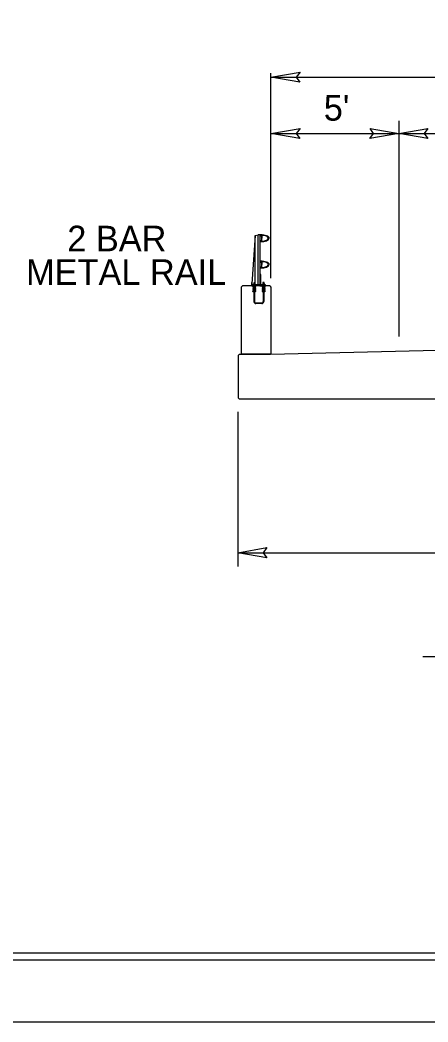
# Model space of a CAD drawing. Extents: x 1734085 to 1734267, y 541107 to 541226.
# Drawn here: x 1734191.61 to 1734207.51, y 541107.08 to 541146.16 of the extents above; entities that cross this region are included whole.
import ezdxf

# ---------------------------------------------------------------- set-up
doc = ezdxf.new("R2010")
doc.units = 0
for name, color, linetype in [('Default', 7, 'Continuous'), ('Prop Dimension', 7, 'Continuous'), ('Prop Terminator CELL', 7, 'Continuous'), ('Sheet Cutting Line CELL', 7, 'Continuous'), ('Sheet Plot Border Inside CELL', 7, 'Continuous'), ('Sheet Plot Border Outside CELL', 7, 'Continuous'), ('Sheet Typical CELL', 7, 'Continuous'), ('Typical Bridge Rail Two Bar CELL', 7, 'Continuous'), ('Typical Slope Point Local CELL', 7, 'Continuous'), ('Typical Text Label CELL', 7, 'Continuous')]:
    doc.layers.add(name, color=color, linetype=linetype)

msp = doc.modelspace()

# ---------------------------------------------------------------- linework, layer by layer
at = {"layer": 'Default'}
for p, q in [((1734200.102, 541130.874), (1734200.102, 541124.844)), ((1734200.102, 541125.381), (1734236.662, 541125.381))]:
    msp.add_line(p, q, dxfattribs=at)
at = {"layer": 'Prop Dimension'}
for p, q in [((1734201.393, 541136.094), (1734201.393, 541144.088)), ((1734201.393, 541143.929), (1734235.365, 541143.929)), ((1734206.379, 541142.237), (1734206.379, 541133.819)), ((1734201.393, 541141.737), (1734206.379, 541141.737)), ((1734206.379, 541141.737), (1734218.381, 541141.737))]:
    msp.add_line(p, q, dxfattribs=at)
at = {"layer": 'Prop Terminator CELL'}
for points in [[(1734202.518, 541143.735), (1734201.393, 541143.929), (1734202.524, 541144.129), (1734202.38, 541143.929)], [(1734202.518, 541141.543), (1734201.393, 541141.737), (1734202.524, 541141.937), (1734202.38, 541141.737)], [(1734205.254, 541141.931), (1734206.379, 541141.737), (1734205.247, 541141.537), (1734205.391, 541141.737)], [(1734207.504, 541141.543), (1734206.379, 541141.737), (1734207.51, 541141.937), (1734207.366, 541141.737)], [(1734201.227, 541125.188), (1734200.102, 541125.381), (1734201.233, 541125.581), (1734201.089, 541125.381)]]:
    msp.add_lwpolyline(points, close=True, dxfattribs=at)
at = {"layer": 'Sheet Cutting Line CELL'}
msp.add_line((1734084.641, 541107.075), (1734266.513, 541107.075), dxfattribs=at)
at = {"layer": 'Sheet Plot Border Inside CELL'}
msp.add_lwpolyline([(1734266.027, 541223.451), (1734086.045, 541223.451), (1734086.045, 541109.5), (1734266.027, 541109.5)], close=True, dxfattribs=at)
at = {"layer": 'Sheet Plot Border Outside CELL'}
msp.add_lwpolyline([(1734266.513, 541225.875), (1734084.641, 541225.875), (1734084.641, 541107.075), (1734266.513, 541107.075)], close=True, dxfattribs=at)
at = {"layer": 'Sheet Typical CELL'}
msp.add_lwpolyline([(1734264.677, 541223.175), (1734102.677, 541223.175), (1734102.677, 541109.775), (1734264.677, 541109.775)], close=True, dxfattribs=at)
at = {"layer": 'Typical Bridge Rail Two Bar CELL'}
for p, q in [((1734200.778, 541137.751), (1734200.641, 541135.868)), ((1734200.778, 541137.751), (1734200.897, 541137.789)), ((1734200.778, 541135.829), (1734200.778, 541137.751)), ((1734200.975, 541137.789), (1734200.897, 541137.789)), ((1734200.897, 541135.829), (1734200.897, 541137.789)), ((1734200.975, 541135.829), (1734200.975, 541137.789)), ((1734201.041, 541137.757), (1734201.041, 541137.65)), ((1734201.041, 541137.544), (1734201.041, 541137.65)), ((1734200.778, 541136.851), (1734200.774, 541136.851)), ((1734201.041, 541136.729), (1734201.041, 541136.623)), ((1734201.041, 541136.516), (1734201.041, 541136.623)), ((1734200.226, 541135.739), (1734200.277, 541135.789)), ((1734201.342, 541135.789), (1734200.277, 541135.789)), ((1734200.641, 541135.829), (1734200.641, 541135.868)), ((1734200.645, 541135.89), (1734200.645, 541135.924)), ((1734200.717, 541135.742), (1734200.717, 541135.829)), ((1734200.762, 541135.908), (1734200.718, 541135.908)), ((1734200.718, 541135.908), (1734200.718, 541135.871)), ((1734200.762, 541135.871), (1734200.762, 541135.908)), ((1734200.762, 541135.742), (1734200.762, 541135.829)), ((1734201.078, 541135.752), (1734201.078, 541135.839)), ((1734201.126, 541135.918), (1734201.081, 541135.918)), ((1734201.081, 541135.918), (1734201.081, 541135.881)), ((1734201.126, 541135.881), (1734201.126, 541135.918)), ((1734201.128, 541135.752), (1734201.128, 541135.839)), ((1734201.342, 541135.789), (1734201.393, 541135.739)), ((1734200.226, 541135.739), (1734200.226, 541133.123)), ((1734200.791, 541135.752), (1734200.687, 541135.752)), ((1734200.791, 541135.74), (1734200.687, 541135.74)), ((1734200.73, 541135.706), (1734200.687, 541135.706)), ((1734200.73, 541135.694), (1734200.687, 541135.694)), ((1734200.73, 541135.659), (1734200.687, 541135.659)), ((1734200.73, 541135.647), (1734200.687, 541135.647)), ((1734200.73, 541135.613), (1734200.687, 541135.613)), ((1734200.73, 541135.602), (1734200.687, 541135.602)), ((1734200.73, 541135.567), (1734200.687, 541135.567)), ((1734200.73, 541135.555), (1734200.687, 541135.555)), ((1734200.73, 541135.728), (1734200.709, 541135.728)), ((1734200.73, 541135.717), (1734200.709, 541135.717)), ((1734200.73, 541135.682), (1734200.709, 541135.682)), ((1734200.73, 541135.671), (1734200.709, 541135.671)), ((1734200.73, 541135.636), (1734200.709, 541135.636)), ((1734200.73, 541135.625), (1734200.709, 541135.625)), ((1734200.73, 541135.59), (1734200.709, 541135.59)), ((1734200.73, 541135.578), (1734200.709, 541135.578)), ((1734200.747, 541135.729), (1734200.73, 541135.729)), ((1734200.73, 541135.729), (1734200.73, 541135.176)), ((1734200.747, 541135.729), (1734200.747, 541135.176)), ((1734200.768, 541135.728), (1734200.747, 541135.728)), ((1734200.768, 541135.717), (1734200.747, 541135.717)), ((1734200.791, 541135.706), (1734200.747, 541135.706)), ((1734200.791, 541135.694), (1734200.747, 541135.694)), ((1734200.768, 541135.682), (1734200.747, 541135.682)), ((1734200.768, 541135.671), (1734200.747, 541135.671)), ((1734200.791, 541135.659), (1734200.747, 541135.659)), ((1734200.791, 541135.647), (1734200.747, 541135.647)), ((1734200.768, 541135.636), (1734200.747, 541135.636)), ((1734200.768, 541135.625), (1734200.747, 541135.625)), ((1734200.791, 541135.613), (1734200.747, 541135.613)), ((1734200.791, 541135.602), (1734200.747, 541135.602)), ((1734200.768, 541135.59), (1734200.747, 541135.59)), ((1734200.768, 541135.578), (1734200.747, 541135.578)), ((1734200.791, 541135.567), (1734200.747, 541135.567)), ((1734200.791, 541135.555), (1734200.747, 541135.555)), ((1734201.153, 541135.752), (1734201.049, 541135.752)), ((1734201.153, 541135.74), (1734201.049, 541135.74)), ((1734201.093, 541135.706), (1734201.049, 541135.706)), ((1734201.093, 541135.694), (1734201.049, 541135.694)), ((1734201.093, 541135.659), (1734201.049, 541135.659)), ((1734201.093, 541135.647), (1734201.049, 541135.647)), ((1734201.093, 541135.613), (1734201.049, 541135.613)), ((1734201.093, 541135.602), (1734201.049, 541135.602)), ((1734201.093, 541135.567), (1734201.049, 541135.567)), ((1734201.093, 541135.555), (1734201.049, 541135.555)), ((1734201.093, 541135.728), (1734201.072, 541135.728)), ((1734201.093, 541135.717), (1734201.072, 541135.717)), ((1734201.093, 541135.682), (1734201.072, 541135.682)), ((1734201.093, 541135.671), (1734201.072, 541135.671)), ((1734201.093, 541135.636), (1734201.072, 541135.636)), ((1734201.093, 541135.625), (1734201.072, 541135.625)), ((1734201.093, 541135.59), (1734201.072, 541135.59)), ((1734201.093, 541135.578), (1734201.072, 541135.578)), ((1734201.093, 541135.729), (1734201.093, 541135.176)), ((1734201.11, 541135.728), (1734201.093, 541135.728)), ((1734201.11, 541135.729), (1734201.11, 541135.176)), ((1734201.13, 541135.728), (1734201.11, 541135.728)), ((1734201.13, 541135.717), (1734201.11, 541135.717)), ((1734201.153, 541135.706), (1734201.11, 541135.706)), ((1734201.153, 541135.694), (1734201.11, 541135.694)), ((1734201.13, 541135.682), (1734201.11, 541135.682)), ((1734201.13, 541135.671), (1734201.11, 541135.671)), ((1734201.153, 541135.659), (1734201.11, 541135.659)), ((1734201.153, 541135.647), (1734201.11, 541135.647)), ((1734201.13, 541135.636), (1734201.11, 541135.636)), ((1734201.13, 541135.625), (1734201.11, 541135.625)), ((1734201.153, 541135.613), (1734201.11, 541135.613)), ((1734201.153, 541135.602), (1734201.11, 541135.602)), ((1734201.13, 541135.59), (1734201.11, 541135.59)), ((1734201.13, 541135.578), (1734201.11, 541135.578)), ((1734201.153, 541135.567), (1734201.11, 541135.567)), ((1734201.153, 541135.555), (1734201.11, 541135.555)), ((1734201.393, 541135.739), (1734201.393, 541133.123)), ((1734201.037, 541135.121), (1734200.803, 541135.121)), ((1734201.037, 541135.104), (1734200.803, 541135.104)), ((1734201.393, 541133.123), (1734200.226, 541133.123))]:
    msp.add_line(p, q, dxfattribs=at)
for points in [[(1734200.975, 541137.515), (1734200.975, 541137.566), (1734200.996, 541137.566), (1734200.996, 541137.557), (1734200.994, 541137.557), (1734200.994, 541137.536), (1734201.028, 541137.536), (1734201.032, 541137.568), (1734201.032, 541137.65), (1734201.032, 541137.732), (1734201.028, 541137.765), (1734200.994, 541137.765), (1734200.994, 541137.744), (1734200.996, 541137.744), (1734200.996, 541137.735), (1734200.975, 541137.735), (1734200.975, 541137.787)], [(1734200.975, 541136.487), (1734200.975, 541136.538), (1734200.996, 541136.538), (1734200.996, 541136.529), (1734200.994, 541136.529), (1734200.994, 541136.508), (1734201.028, 541136.508), (1734201.032, 541136.541), (1734201.032, 541136.623), (1734201.032, 541136.705), (1734201.028, 541136.737), (1734200.994, 541136.737), (1734200.994, 541136.716), (1734200.996, 541136.716), (1734200.996, 541136.708), (1734200.975, 541136.708), (1734200.975, 541136.759)], [(1734201.176, 541135.789), (1734201.176, 541135.839), (1734200.995, 541135.839), (1734200.995, 541136.241), (1734200.975, 541136.241), (1734200.975, 541135.829), (1734200.65, 541135.829), (1734200.65, 541135.858), (1734200.641, 541135.858), (1734200.641, 541135.789), (1734200.798, 541135.789), (1734200.798, 541135.817), (1734200.955, 541135.817), (1734200.955, 541135.789), (1734201.176, 541135.789)], [(1734200.784, 541135.828), (1734200.784, 541135.837), (1734200.74, 541135.837), (1734200.695, 541135.837), (1734200.695, 541135.828)], [(1734200.773, 541135.837), (1734200.773, 541135.866), (1734200.767, 541135.871), (1734200.712, 541135.871), (1734200.707, 541135.866), (1734200.707, 541135.837), (1734200.773, 541135.837), (1734200.751, 541135.837), (1734200.751, 541135.866), (1734200.756, 541135.871), (1734200.751, 541135.866), (1734200.746, 541135.871), (1734200.734, 541135.871), (1734200.729, 541135.866), (1734200.729, 541135.837), (1734200.729, 541135.866), (1734200.723, 541135.871)], [(1734201.149, 541135.838), (1734201.149, 541135.847), (1734201.104, 541135.847), (1734201.059, 541135.847), (1734201.059, 541135.838)], [(1734201.136, 541135.847), (1734201.136, 541135.875), (1734201.131, 541135.881), (1734201.075, 541135.881), (1734201.07, 541135.875), (1734201.07, 541135.847), (1734201.136, 541135.847), (1734201.114, 541135.847), (1734201.114, 541135.875), (1734201.12, 541135.881), (1734201.114, 541135.875), (1734201.109, 541135.881), (1734201.097, 541135.881), (1734201.092, 541135.875), (1734201.092, 541135.847), (1734201.092, 541135.875), (1734201.087, 541135.881)], [(1734200.687, 541135.752), (1734200.687, 541135.74), (1734200.709, 541135.728), (1734200.709, 541135.717), (1734200.687, 541135.706), (1734200.687, 541135.694), (1734200.709, 541135.682), (1734200.709, 541135.671), (1734200.687, 541135.659), (1734200.687, 541135.647), (1734200.709, 541135.636), (1734200.709, 541135.625), (1734200.687, 541135.613), (1734200.687, 541135.602), (1734200.709, 541135.59), (1734200.709, 541135.578), (1734200.687, 541135.567), (1734200.687, 541135.555)], [(1734200.791, 541135.752), (1734200.791, 541135.74), (1734200.768, 541135.728), (1734200.768, 541135.717), (1734200.791, 541135.706), (1734200.791, 541135.694), (1734200.768, 541135.682), (1734200.768, 541135.671), (1734200.791, 541135.659), (1734200.791, 541135.647), (1734200.768, 541135.636), (1734200.768, 541135.625), (1734200.791, 541135.613), (1734200.791, 541135.602), (1734200.768, 541135.59), (1734200.768, 541135.578), (1734200.791, 541135.567), (1734200.791, 541135.555)], [(1734201.049, 541135.752), (1734201.049, 541135.74), (1734201.072, 541135.728), (1734201.072, 541135.717), (1734201.049, 541135.706), (1734201.049, 541135.694), (1734201.072, 541135.682), (1734201.072, 541135.671), (1734201.049, 541135.659), (1734201.049, 541135.647), (1734201.072, 541135.636), (1734201.072, 541135.625), (1734201.049, 541135.613), (1734201.049, 541135.602), (1734201.072, 541135.59), (1734201.072, 541135.578), (1734201.049, 541135.567), (1734201.049, 541135.555)], [(1734201.154, 541135.752), (1734201.154, 541135.74), (1734201.13, 541135.728), (1734201.13, 541135.717), (1734201.154, 541135.706), (1734201.154, 541135.694), (1734201.13, 541135.682), (1734201.13, 541135.671), (1734201.154, 541135.659), (1734201.154, 541135.647), (1734201.13, 541135.636), (1734201.13, 541135.625), (1734201.154, 541135.613), (1734201.154, 541135.602), (1734201.13, 541135.59), (1734201.13, 541135.578), (1734201.154, 541135.567), (1734201.154, 541135.555)]]:
    msp.add_lwpolyline(points, dxfattribs=at)
for centre in [(1734200.696, 541135.584), (1734201.145, 541135.584)]:
    msp.add_circle(centre, 0.00868, dxfattribs=at)
for centre, radius, start, end in [((1734201.049, 541137.757), 0.00815, 90, 180), ((1734201.049, 541137.544), 0.00815, 180, 270), ((1734201.049, 541136.729), 0.00815, 90, 180), ((1734201.049, 541136.516), 0.00815, 180, 270), ((1734200.803, 541135.176), 0.0729, 180, 270), ((1734200.803, 541135.176), 0.0556, 180, 270), ((1734201.037, 541135.176), 0.0556, 270, 0), ((1734201.037, 541135.176), 0.0729, 270, 0)]:
    msp.add_arc(centre, radius, start, end, dxfattribs=at)
for centre, major_axis, ratio, start_param, end_param in [((1734200.975, 541137.65), (0.348, 0), 0.39036, 6.282787, 7.853967), ((1734201.049, 541137.65), (0.231, 0), 0.495501, 6.282718, 7.853881), ((1734200.975, 541137.65), (0.348, 0), 0.39036, 4.712404, 6.282787), ((1734201.049, 541137.65), (0.231, 0), 0.495501, 4.712489, 6.282718), ((1734200.975, 541136.623), (0.348, 0), 0.39036, 6.282787, 7.853967), ((1734200.975, 541136.623), (0.348, 0), 0.39036, 4.712404, 6.282787), ((1734201.049, 541136.623), (0.231, 0), 0.495501, 6.282718, 7.853881), ((1734201.049, 541136.623), (0.231, 0), 0.495501, 4.712489, 6.282718)]:
    msp.add_ellipse(centre, major_axis=major_axis, ratio=ratio, start_param=start_param, end_param=end_param, dxfattribs=at)
at = {"layer": 'Typical Slope Point Local CELL'}
for p, q in [((1734201.379, 541133.123), (1734218.379, 541133.548)), ((1734200.161, 541133.123), (1734200.129, 541133.09)), ((1734200.129, 541131.405), (1734200.129, 541133.09)), ((1734200.161, 541133.123), (1734201.379, 541133.123)), ((1734200.129, 541131.405), (1734200.155, 541131.379)), ((1734200.155, 541131.379), (1734236.602, 541131.379))]:
    msp.add_line(p, q, dxfattribs=at)
at = {"layer": 'Typical Text Label CELL'}
msp.add_line((1734207.311, 541121.329), (1734228.915, 541121.329), dxfattribs=at)

# ---------------------------------------------------------------- texts
at = {"layer": 'Prop Dimension'}
for s, p in [("5'", (1734203.45, 541142.237)), ('2 BAR', (1734193.452, 541137.139)), ('METAL RAIL', (1734191.847, 541135.828))]:
    msp.add_text(s, height=1, dxfattribs=at).set_placement(p)

doc.saveas('drawing.dxf')
